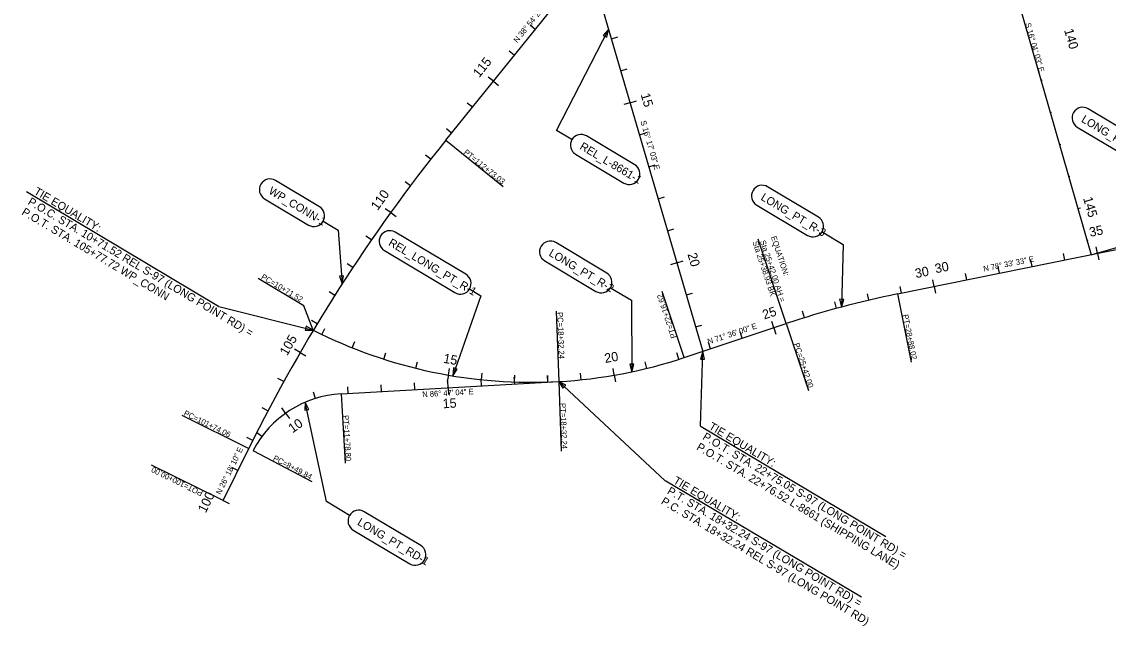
# Model space of a CAD drawing. Extents: x 2339300 to 2355400, y 360879 to 381052.
# Drawn here: x 2344787 to 2348046, y 366396 to 368208 of the extents above; entities that cross this region are included whole.
import ezdxf

# ---------------------------------------------------------------- set-up
doc = ezdxf.new("R2010")
doc.units = 0
for name, color, linetype in [('RD_HC_Cl', 7, 'Continuous'), ('RD_HC_Data', 7, 'Continuous'), ('RD_HC_Data_Rel', 7, 'Continuous'), ('RD_HC_Data_Tic', 7, 'Continuous'), ('RD_HC_Data_Tic_Rel', 7, 'Continuous'), ('RD_HC_TX_Rel_Sta50', 7, 'Continuous'), ('RD_HC_TX_Sta50', 7, 'Continuous')]:
    doc.layers.add(name, color=color, linetype=linetype)

msp = doc.modelspace()

# ---------------------------------------------------------------- linework, layer by layer
at = {"layer": 'RD_HC_Cl'}
for p, q in [((2347639.2, 368747.8), (2347994.6, 367509.7)), ((2346059.3, 367853.2), (2346703.6, 368651.5)), ((2346471.7, 368445.2), (2346829.6, 367219.9)), ((2347414.1, 367392.2), (2348105.3, 367532.1)), ((2346774.2, 367201.5), (2347080, 367303.2)), ((2345745.3, 367092.9), (2346397.7, 367129.6)), ((2345391.2, 366773.2), (2345468.3, 366929.3))]:
    msp.add_line(p, q, dxfattribs=at)
for centre, radius, start, end in [((2349947, 364715.5), 4996, 141.0938, 153.6971), ((2347979.2, 364600.1), 2848.8, 101.4407, 108.4001), ((2346316.3, 368577.7), 1450.4, 273.2156, 288.4001), ((2345763.2, 366774.4), 319, 93.2156, 152.2947)]:
    msp.add_arc(centre, radius, start, end, dxfattribs=at)
at = {"layer": 'RD_HC_Data'}
for p, q in [((2348157.2, 367845), (2347985.9, 367947.3)), ((2347953.1, 367892.3), (2348124.5, 367790.1)), ((2346059.3, 367853.2), (2346230.8, 367714.7)), ((2346625.7, 367779.7), (2346481.3, 367865.9)), ((2346448.5, 367810.9), (2346592.9, 367724.8)), ((2345679.8, 367653.8), (2345548, 367732.4)), ((2347176.6, 367622.7), (2347024.5, 367713.4)), ((2345377.1, 367354.9), (2344801.4, 367698.4)), ((2345515.3, 367677.5), (2345647, 367598.8)), ((2346991.7, 367658.5), (2347143.8, 367567.7)), ((2346119.2, 367451.1), (2345907.5, 367577.4)), ((2347080, 367303.2), (2346995.8, 367556.2)), ((2345874.7, 367522.4), (2346086.4, 367396.1)), ((2346541.8, 367454.8), (2346388.7, 367546.2)), ((2347994.6, 367509.7), (2348120.3, 367545.8)), ((2346355.9, 367491.2), (2346509, 367399.8)), ((2346774.2, 367201.5), (2346708.4, 367399.2)), ((2347414.1, 367392.2), (2347455.5, 367188)), ((2346390.4, 367340.8), (2346397.7, 367129.6)), ((2347080, 367303.2), (2347146.7, 367102.6)), ((2345745.3, 367092.9), (2345757, 366884.6)), ((2345266.9, 367028.8), (2345468.3, 366929.3)), ((2347378.8, 366663.7), (2346825.5, 366993.8)), ((2345480.7, 366922.7), (2345656.8, 366830.3)), ((2345391.2, 366773.2), (2345176.7, 366879.2)), ((2347306, 366483.3), (2346719.1, 366831.1)), ((2345983.8, 366638.1), (2345814.1, 366739.3)), ((2345781.4, 366684.3), (2345951, 366583.1))]:
    msp.add_line(p, q, dxfattribs=at)
for points in [[(2346437.4, 367854.8), (2346391.6, 367882.1), (2346547.6, 368185.1)], [(2345690.9, 367609.9), (2345736, 367583), (2345748.1, 367422.7)], [(2347187.7, 367578.8), (2347251.5, 367540.7), (2347245.7, 367352.8)], [(2346130.3, 367407.2), (2346164.3, 367386.9), (2346080, 367146.7)], [(2346552.9, 367410.9), (2346616.2, 367373.2), (2346617.3, 367158.9)], [(2345377.1, 367354.9), (2345378.5, 367354.1), (2345661.6, 367283.5)], [(2346825.5, 366993.8), (2346823, 366995.3), (2346829.6, 367219.9)], [(2346719.1, 366831.1), (2346717.5, 366832), (2346397.7, 367129.6)], [(2345770.3, 366728.2), (2345700.9, 366769.6), (2345637, 367067.4)]]:
    msp.add_lwpolyline(points, dxfattribs=at)
for points in [[(2346542.5, 368161.7), (2346547.6, 368185.1), (2346531.5, 368167.4)], [(2345740.2, 367445.4), (2345748.1, 367422.7), (2345752.6, 367446.3)], [(2347240.2, 367376.2), (2347245.7, 367352.8), (2347252.6, 367375.8)], [(2345637.6, 367283.1), (2345661.6, 367283.5), (2345640.6, 367295.2)], [(2346835.1, 367196.6), (2346829.6, 367219.9), (2346822.7, 367196.9)], [(2346081.8, 367170.6), (2346080, 367146.7), (2346093.6, 367166.5)], [(2346611, 367182), (2346617.3, 367158.9), (2346623.4, 367182.1)], [(2346418.9, 367118.4), (2346397.7, 367129.6), (2346410.4, 367109.3)], [(2345647.9, 367046.1), (2345637, 367067.4), (2345635.8, 367043.5)]]:
    msp.add_lwpolyline(points, close=True, dxfattribs=at)
for centre, start, end in [((2347969.5, 367919.8), 59.1784, 239.1784), ((2346464.9, 367838.4), 59.1784, 239.1784), ((2346609.3, 367752.2), 239.1784, 59.1784), ((2345531.7, 367704.9), 59.1784, 239.1784), ((2347008.1, 367685.9), 59.1784, 239.1784), ((2345663.4, 367626.3), 239.1784, 59.1784), ((2347160.2, 367595.2), 239.1784, 59.1784), ((2345891.1, 367549.9), 59.1784, 239.1784), ((2346372.3, 367518.7), 59.1784, 239.1784), ((2346102.8, 367423.6), 239.1784, 59.1784), ((2346525.4, 367427.3), 239.1784, 59.1784), ((2345797.7, 366711.8), 59.1784, 239.1784), ((2345967.4, 366610.6), 239.1784, 59.1784)]:
    msp.add_arc(centre, 32, start, end, dxfattribs=at)
at = {"layer": 'RD_HC_Data_Rel'}
msp.add_line((2346397.7, 367129.6), (2346404.9, 366921.2), dxfattribs=at)
msp.add_lwpolyline([(2345661.6, 367283.5), (2345633.5, 367357), (2345496.2, 367438.9)], dxfattribs=at)
msp.add_arc((2346316.3, 368577.7), 1450.4, 243.1643, 273.2156, dxfattribs=at)
at = {"layer": 'RD_HC_Data_Tic'}
for p, q in [((2346327.4, 368185.4), (2346311.9, 368198)), ((2346555.8, 368157.3), (2346575, 368162.9)), ((2346264.6, 368107.6), (2346249.1, 368120.2)), ((2347816.9, 368128.7), (2347824.6, 368130.9)), ((2346201.8, 368029.8), (2346186.3, 368042.4)), ((2346583.8, 368061.3), (2346603, 368066.9)), ((2346201.8, 368029.8), (2346217.4, 368017.2)), ((2347844.5, 368032.6), (2347848.4, 368033.7)), ((2346611.9, 367965.3), (2346631.1, 367970.9)), ((2346139, 367952), (2346123.5, 367964.6)), ((2346611.9, 367965.3), (2346592.7, 367959.7)), ((2347872.1, 367936.5), (2347875.9, 367937.6)), ((2346076.2, 367874.2), (2346060.7, 367886.7)), ((2346639.9, 367869.3), (2346659.1, 367874.9)), ((2347899.7, 367840.3), (2347903.5, 367841.4)), ((2346013.8, 367796), (2345998.1, 367808.4)), ((2346667.9, 367773.3), (2346687.1, 367778.9)), ((2347927.3, 367744.2), (2347931.1, 367745.3)), ((2345953, 367716.7), (2345937, 367728.7)), ((2346696, 367677.3), (2346715.2, 367682.9)), ((2345893.7, 367636.1), (2345877.5, 367647.8)), ((2347954.9, 367648.1), (2347962.6, 367650.3)), ((2345893.7, 367636.1), (2345909.9, 367624.5)), ((2346724, 367581.3), (2346743.2, 367586.9)), ((2345836, 367554.4), (2345819.6, 367565.8)), ((2347982.5, 367552), (2347986.3, 367553.1)), ((2348014, 367513.6), (2348010, 367533.2)), ((2348014, 367513.6), (2348017.9, 367494)), ((2345780, 367471.6), (2345763.4, 367482.6)), ((2346752.1, 367485.3), (2346732.9, 367479.7)), ((2346752.1, 367485.3), (2346771.3, 367491)), ((2347817.9, 367474), (2347814, 367493.6)), ((2347916, 367493.8), (2347912, 367513.4)), ((2347621.9, 367434.3), (2347617.9, 367453.9)), ((2347719.9, 367454.1), (2347716, 367473.7)), ((2347523.9, 367414.5), (2347519.9, 367434.1)), ((2345725.7, 367387.6), (2345708.8, 367398.3)), ((2346780.1, 367389.4), (2346799.3, 367395)), ((2347328.2, 367373.5), (2347323.6, 367392.9)), ((2347425.9, 367394.6), (2347421.9, 367414.2)), ((2347523.9, 367414.5), (2347527.9, 367394.9)), ((2347231.2, 367348.9), (2347226, 367368.2)), ((2347135.2, 367321), (2347129.3, 367340.1)), ((2345673.1, 367302.6), (2345656, 367313)), ((2346808.1, 367293.4), (2346827.3, 367299)), ((2347043.1, 367290.9), (2347036.7, 367309.9)), ((2347043.1, 367290.9), (2347049.4, 367271.9)), ((2346948.2, 367259.4), (2346941.9, 367278.3)), ((2345622.2, 367216.5), (2345604.8, 367226.6)), ((2346853.3, 367227.8), (2346847, 367246.8)), ((2345622.2, 367216.5), (2345639.5, 367206.5)), ((2346662.1, 367169.1), (2346657.4, 367188.6)), ((2346758.4, 367196.3), (2346752.3, 367215.4)), ((2346564.3, 367148.7), (2346560.9, 367168.4)), ((2345573, 367129.5), (2345555.5, 367139.1)), ((2345966.1, 367105.4), (2345965, 367125.3)), ((2346066, 367111), (2346064.9, 367130.9)), ((2346165.8, 367116.6), (2346164.7, 367136.5)), ((2346265.7, 367122.2), (2346264.5, 367142.2)), ((2346365.5, 367127.8), (2346364.4, 367147.8)), ((2346465.2, 367135), (2346463.2, 367154.9)), ((2346564.3, 367148.7), (2346567.7, 367129)), ((2345668, 367078.9), (2345662, 367098)), ((2345766.5, 367094.1), (2345765.3, 367114.1)), ((2345866.3, 367099.7), (2345865.2, 367119.7)), ((2346066, 367111), (2346067.1, 367091)), ((2345525.5, 367041.5), (2345507.8, 367050.8)), ((2345578.7, 367034.7), (2345567.1, 367051)), ((2345578.7, 367034.7), (2345590.3, 367018.4)), ((2345479.9, 366952.5), (2345462, 366961.5)), ((2345507.4, 366965.1), (2345491.4, 366977.1)), ((2345435.5, 366862.9), (2345417.6, 366871.7)), ((2345391.2, 366773.2), (2345373.2, 366782.1)), ((2345391.2, 366773.2), (2345409.1, 366764.4))]:
    msp.add_line(p, q, dxfattribs=at)
at = {"layer": 'RD_HC_Data_Tic_Rel'}
for p, q in [((2345687.1, 367270.9), (2345695.8, 367288.9)), ((2345778.6, 367230.7), (2345786.1, 367249.2)), ((2345872.7, 367196.8), (2345878.8, 367215.9)), ((2345968.9, 367169.5), (2345973.7, 367189)), ((2346066.7, 367149), (2346070.2, 367168.7)), ((2346066.7, 367149), (2346063.3, 367129.3)), ((2346165.8, 367135.2), (2346167.8, 367155)), ((2346265.5, 367128.2), (2346266.2, 367148.2)), ((2346365.5, 367128.2), (2346364.8, 367148.1))]:
    msp.add_line(p, q, dxfattribs=at)

# ---------------------------------------------------------------- texts
at = {"layer": 'RD_HC_Data'}
for s, height, rotation, p in [('N 38%%d 54\' 22" E', 17, 51.0938, (2346273.5, 368143.7)), ('S 16%%d 01\' 03" E', 17, 286.0174, (2347796.7, 368202.6)), ('S 16%%d 17\' 03" E', 17, 286.2842, (2346642.8, 367909.3)), ('LONG_PT_RD-4', 24, 329.1784, (2347963.3, 367909.5)), ('REL_L-8661-1', 24, 329.1784, (2346458.8, 367828.1)), ('PT=112+73.03', 17, 321.0938, (2346111.1, 367813.9)), ('TIE EQUALITY:', 24, 329.1784, (2344821.6, 367693.3)), ('WP_CONN-1', 24, 329.1784, (2345525.5, 367694.6)), ('P.O.C. STA. 10+71.52 REL S-97 (LONG POINT RD) =', 24, 329.1784, (2344803.2, 367662.4)), ('LONG_PT_R-3', 24, 329.1784, (2347001.9, 367675.6)), ('P.O.T. STA. 105+77.72 WP_CONN', 24, 329.1784, (2344784.7, 367631.5)), ('REL_LONG_PT_R-1', 24, 329.1784, (2345885, 367539.6)), ('Sta 25+38.93 BK', 17, 288.4001, (2346978.8, 367547.2)), ('Sta 25+42.00 AH =', 17, 288.4001, (2347001.2, 367550)), ('EQUATION:', 17, 288.4001, (2347034, 367562.6)), ('LONG_PT_R-2', 24, 329.1784, (2346366.1, 367508.4)), ('N 78%%d 33\' 33" E', 17, 11.4407, (2347673.3, 367459)), ('PT=22+16.62', 17, 108.4001, (2346751.7, 367262.5)), ('PC=18+32.24', 17, 271.9671, (2346393.4, 367337.3)), ('PT=28+88.02', 17, 281.4407, (2347429, 367328.9)), ('N 71%%d 36\' 00" E', 17, 18.4001, (2346847.4, 367240.6)), ('PC=25+42.00', 17, 288.4001, (2347102.4, 367242.2)), ('N 86%%d 47\' 04" E', 17, 3.2156, (2345988.9, 367082.7)), ('PC=101+74.06', 17, 333.6971, (2345271.3, 367029)), ('PT=11+78.80', 17, 273.2156, (2345750.9, 367028.2)), ('TIE EQUALITY:', 24, 329.1784, (2346845.8, 366988.7)), ('P.O.T. STA. 22+75.05 S-97 (LONG POINT RD) =', 24, 329.1784, (2346827.3, 366957.8)), ('N 26%%d 18\' 10" E', 17, 63.6971, (2345383.5, 366789.2)), ('P.O.T. STA. 22+76.52 L-8661 (SHIPPING LANE)', 24, 329.1784, (2346808.9, 366926.9)), ('PC=8+49.84', 17, 332.2947, (2345539.2, 366894.3)), ('POT=100+00.00', 17, 153.6971, (2345332, 366800.2)), ('TIE EQUALITY:', 24, 329.3534, (2346739.3, 366826)), ('P.T. STA. 18+32.24 S-97 (LONG POINT RD) =', 24, 329.3534, (2346721, 366795)), ('P.C. STA. 18+32.24 REL S-97 (LONG POINT RD)', 24, 329.3534, (2346702.6, 366764.1)), ('LONG_PT_RD-1', 24, 329.1784, (2345791.6, 366701.5))]:
    msp.add_text(s, height=height, rotation=rotation, dxfattribs=at).set_placement(p)
at = {"layer": 'RD_HC_Data_Rel'}
for s, rotation, p in [('PC=10+71.52', 329.1784, (2345503.5, 367438.6)), ('PT=18+32.24', 271.9671, (2346401.9, 367064.7))]:
    msp.add_text(s, height=17, rotation=rotation, dxfattribs=at).set_placement(p)
at = {"layer": 'RD_HC_TX_Rel_Sta50'}
msp.add_text('15', height=28, rotation=350.0908, dxfattribs=at).set_placement((2346050.2, 367186))
at = {"layer": 'RD_HC_TX_Sta50'}
for s, rotation, p in [('140', 286.0174, (2347913.5, 368183.5)), ('115', 51.0938, (2346159.2, 368038.9)), ('15', 286.2842, (2346643.4, 367989.9)), ('110', 54.2249, (2345854.7, 367640.9)), ('145', 286.0174, (2347970.5, 367679.2)), ('35', 11.4407, (2347992.2, 367563.2)), ('20', 286.2842, (2346783.8, 367511.2)), ('30', 11.4407, (2347529.1, 367454)), ('30', 11.4407, (2347469.4, 367439.5)), ('25', 18.4001, (2347014.2, 367315.4)), ('105', 59.9591, (2345583.1, 367205.1)), ('20', 9.8428, (2346537.3, 367185.1)), ('15', 3.2156, (2346050.4, 367049.3)), ('10', 35.3268, (2345599.3, 366974)), ('100', 63.6971, (2345338.8, 366733.9))]:
    msp.add_text(s, height=28, rotation=rotation, dxfattribs=at).set_placement(p)

doc.saveas('drawing.dxf')
